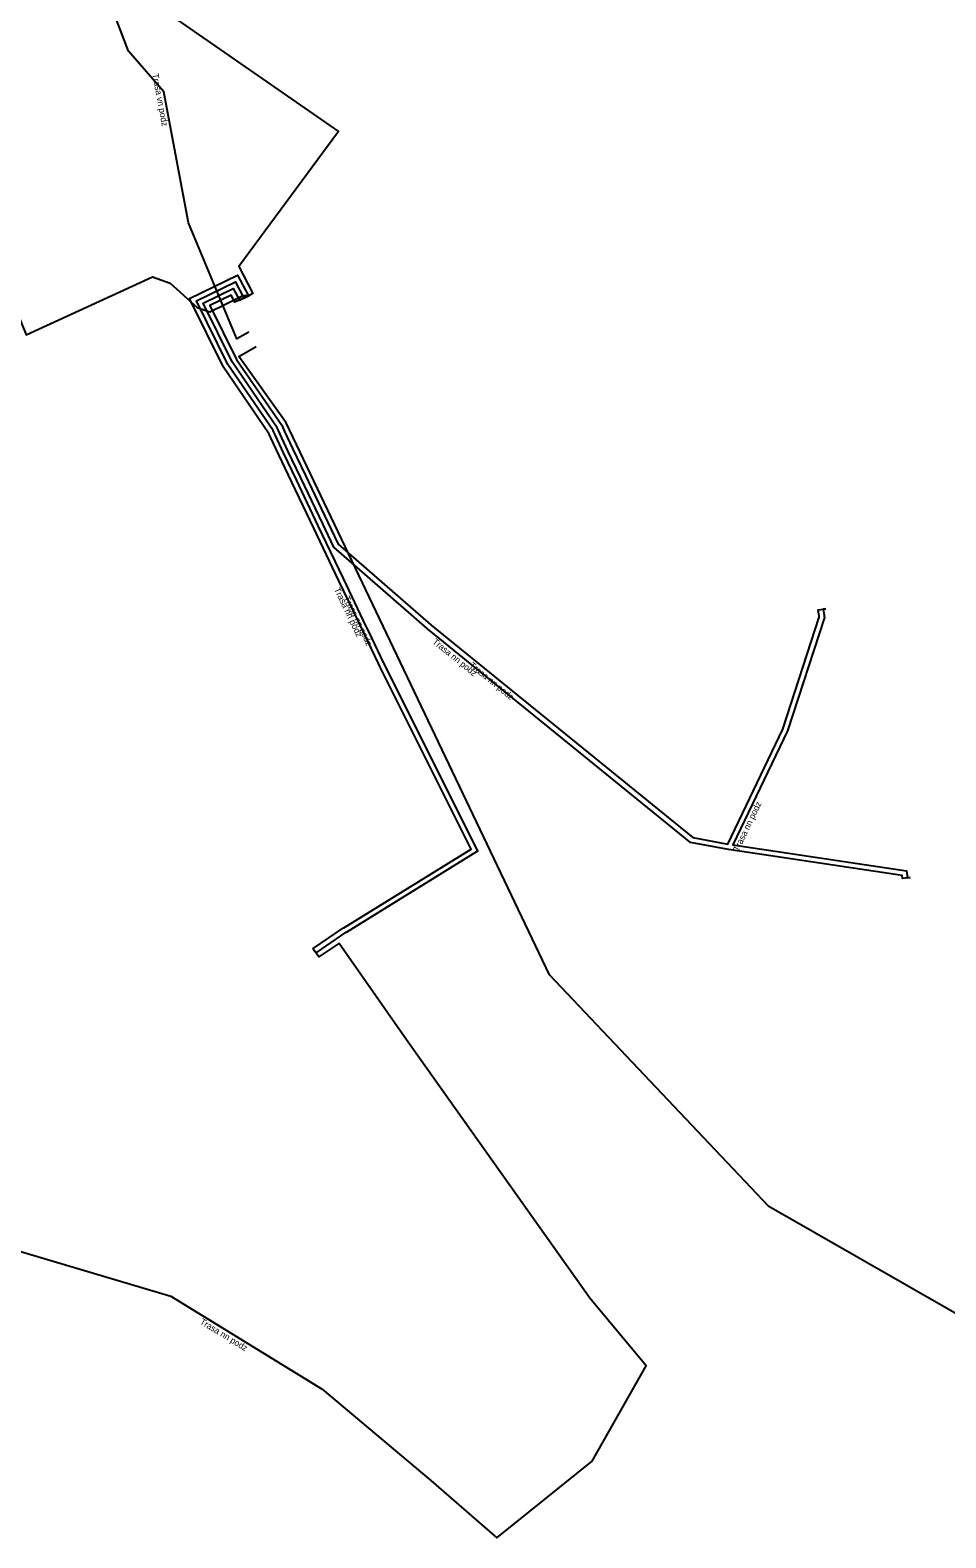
# Model space of a CAD drawing. Extents: x -687449 to -686969, y -975291 to -974892.
# Drawn here: x -687241.3 to -687168.7, y -975147.2 to -975027.7 of the extents above; entities that cross this region are included whole.
import ezdxf

# ---------------------------------------------------------------- set-up
doc = ezdxf.new("R2010")
doc.units = 0
for name, color, linetype in [('Popiskový text - Ostatní atributy Trasy', 7, 'Continuous'), ('Spojnice NN', 7, 'Continuous'), ('Spojnice VN', 7, 'Continuous')]:
    doc.layers.add(name, color=color, linetype=linetype)

msp = doc.modelspace()

# ---------------------------------------------------------------- linework, layer by layer
at = {"layer": 'Spojnice NN'}
for points in [[(-687263.6, -975021.12), (-687258.46, -975025.73), (-687256.33, -975028.07), (-687250.44, -975033.29), (-687248.55, -975035.62), (-687247.3, -975038.26), (-687246.7, -975040.02), (-687245.66, -975042.12), (-687244.07, -975045.98), (-687242.77, -975048.89), (-687241.58, -975051.83), (-687231.55, -975047.24), (-687230.15, -975047.73), (-687228.02, -975049.66), (-687227, -975050.01), (-687225.82, -975049.41), (-687224.4, -975048.7), (-687223.84, -975048.69)], [(-687230.58, -975026.16), (-687216.8, -975035.71), (-687224.72, -975046.41), (-687224.72, -975046.41), (-687223.59, -975048.56), (-687223.84, -975048.69)], [(-687218.71, -975100.65), (-687218.82, -975100.49), (-687216.4, -975098.84), (-687216.39, -975098.84), (-687206.28, -975092.6), (-687213.54, -975078.11), (-687213.65, -975077.88), (-687214.51, -975076.06), (-687215.18, -975074.67), (-687216.78, -975071.32), (-687218.77, -975067.15), (-687220.51, -975063.5), (-687221.54, -975061.35), (-687222.17, -975059.98), (-687222.3, -975059.71), (-687222.35, -975059.61), (-687225.93, -975054.38), (-687228.62, -975048.94), (-687224.81, -975047.1), (-687223.95, -975048.74), (-687223.84, -975048.69)], [(-687218.71, -975100.65), (-687218.59, -975100.82), (-687216.19, -975099.18), (-687216.18, -975099.18), (-687205.76, -975092.74), (-687213.27, -975077.76), (-687213.28, -975077.74), (-687213.28, -975077.74), (-687214.15, -975075.89), (-687214.82, -975074.49), (-687216.42, -975071.15), (-687218.41, -975066.98), (-687220.15, -975063.33), (-687221.18, -975061.18), (-687221.81, -975059.82), (-687221.94, -975059.53), (-687222, -975059.41), (-687225.59, -975054.17), (-687228.08, -975049.13), (-687228.08, -975049.12), (-687224.98, -975047.63), (-687224.98, -975047.64), (-687224.31, -975048.91), (-687223.84, -975048.69)], [(-687171.49, -975094.85), (-687172.09, -975094.93), (-687172.12, -975094.68), (-687185.89, -975092.62), (-687188.89, -975092.07), (-687188.89, -975092.07), (-687209.74, -975075.14), (-687209.77, -975075.12), (-687217.17, -975068.66), (-687218.05, -975066.81), (-687219.79, -975063.16), (-687220.82, -975061.01), (-687221.45, -975059.65), (-687221.58, -975059.36), (-687221.66, -975059.21), (-687225.24, -975053.97), (-687227.55, -975049.31), (-687227.55, -975049.31), (-687227.54, -975049.31), (-687225.16, -975048.16), (-687224.67, -975049.09), (-687223.84, -975048.69)], [(-687223.84, -975048.69), (-687225.03, -975049.25), (-687225.33, -975048.69), (-687227.01, -975049.5), (-687224.89, -975053.77), (-687221.31, -975059), (-687221.22, -975059.18), (-687221.08, -975059.48), (-687220.45, -975060.84), (-687219.43, -975062.99), (-687217.69, -975066.64), (-687216.84, -975068.41), (-687216.84, -975068.42), (-687209.5, -975074.82), (-687209.46, -975074.85), (-687188.72, -975091.69), (-687188.72, -975091.69), (-687185.95, -975092.2), (-687181.59, -975083.09), (-687178.69, -975074.2), (-687178.69, -975074.2), (-687178.7, -975074.14), (-687178.77, -975073.62), (-687178.17, -975073.54)], [(-687178.17, -975073.54), (-687178.37, -975073.57), (-687178.3, -975074.09), (-687178.3, -975074.13), (-687178.28, -975074.23), (-687181.22, -975083.23), (-687185.54, -975092.27), (-687185.54, -975092.27), (-687171.76, -975094.33), (-687171.69, -975094.88), (-687171.49, -975094.85)], [(-687304.62, -975100.33), (-687304.45, -975100.45), (-687304.6, -975100.65), (-687303.85, -975104.98), (-687289.38, -975111.32), (-687281.89, -975113.55), (-687271.53, -975116.3), (-687260.17, -975119.41), (-687251.45, -975121.83), (-687242.64, -975124.31), (-687230.11, -975128.04), (-687218.11, -975135.41), (-687209.5, -975142.66), (-687204.26, -975147.2), (-687196.7, -975141.13), (-687192.41, -975133.57), (-687196.87, -975128.2), (-687210.98, -975108.35), (-687211.42, -975107.71), (-687216.76, -975100.09), (-687216.78, -975100.07), (-687216.78, -975100.07), (-687218.37, -975101.15), (-687218.71, -975100.65)]]:
    msp.add_lwpolyline(points, dxfattribs=at)
at = {"layer": 'Spojnice VN'}
for points in [[(-687223.92, -975051.61), (-687224.87, -975052.14), (-687228.71, -975042.96), (-687230.66, -975032.55), (-687233.46, -975029.35), (-687236.01, -975022.68), (-687239.9, -975016.85)], [(-686971.97, -975081.77), (-686971.81, -975083.32), (-687024.77, -975096.83), (-687030.72, -975085.39), (-687032.26, -975080.74), (-687045.05, -975082.04), (-687041.04, -975101.59), (-687046.03, -975109.05), (-687048.11, -975109.95), (-687141.27, -975134.8), (-687164.81, -975131.15), (-687182.7, -975120.92), (-687200.09, -975102.57), (-687220.96, -975058.81), (-687224.7, -975053.55), (-687223.35, -975052.76)]]:
    msp.add_lwpolyline(points, dxfattribs=at)

# ---------------------------------------------------------------- texts
at = {"layer": 'Popiskový text - Ostatní atributy Trasy'}
for s, rotation, p in [('Trasa vn podz', 280.5934, (-687231.58, -975031.16)), ('Trasa nn podz', 295.5569, (-687217.18, -975072)), ('Trasa nn podz', 295.605, (-687216.41, -975072.68)), ('Trasa nn podz', 320.9203, (-687209.41, -975076.24)), ('Trasa nn podz', 320.9275, (-687206.48, -975078.11)), ('Trasa nn podz', 64.4405, (-687185.09, -975092.83)), ('Trasa nn podz', 328.4354, (-687227.85, -975130.19))]:
    msp.add_text(s, height=0.5, rotation=rotation, dxfattribs=at).set_placement(p)

doc.saveas('drawing.dxf')
